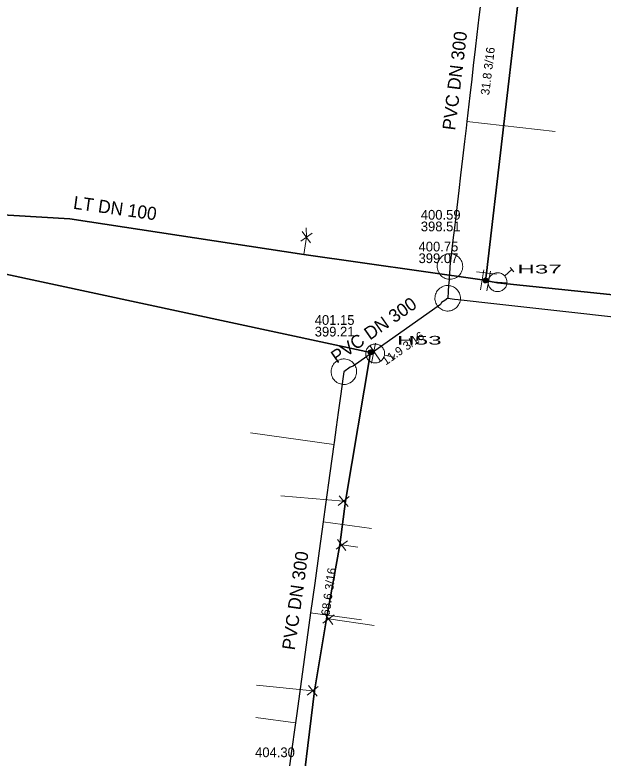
# Model space of a CAD drawing. Extents: x -772952 to -772403, y -1033777 to -1033210.
# Drawn here: x -772682 to -772627.6, y -1033640.4 to -1033571.6 of the extents above; entities that cross this region are included whole.
import ezdxf

# ---------------------------------------------------------------- set-up
doc = ezdxf.new("R2010")
doc.units = 0
doc.header["$LTSCALE"] = 0.36
for name, color, linetype, lineweight in [('15', 7, 'Continuous', 13), ('16', 7, 'Continuous', 35), ('2', 7, 'Continuous', 25), ('20', 7, 'Continuous', 13), ('4', 7, 'Continuous', 13), ('57', 7, 'Continuous', 13), ('59', 7, 'Continuous', 13)]:
    doc.layers.add(name, color=color, linetype=linetype, lineweight=lineweight)
for name, color, linetype in [('17', 7, 'Continuous'), ('3', 7, 'Continuous'), ('6', 7, 'Continuous')]:
    doc.layers.add(name, color=color, linetype=linetype)

msp = doc.modelspace()

# ---------------------------------------------------------------- linework, layer by layer
at = {"layer": '15'}
for p, q in [((-772654.647, -1033592.708), (-772655.418, -1033591.659)), ((-772655.551, -1033592.565), (-772654.509, -1033591.803)), ((-772637.443, -1033595.618), (-772639.293, -1033595.407)), ((-772638.916, -1033597.048), (-772638.603, -1033595.212)), ((-772638.314, -1033597.163), (-772637.977, -1033595.331)), ((-772649.001, -1033603.828), (-772648.632, -1033602.002)), ((-772651.082, -1033616.175), (-772652.077, -1033617.014)), ((-772651.164, -1033617.086), (-772651.993, -1033616.098)), ((-772652.273, -1033621.049), (-772651.237, -1033620.26)), ((-772652.146, -1033620.143), (-772651.367, -1033621.171)), ((-772653.495, -1033627.892), (-772652.455, -1033627.109)), ((-772653.363, -1033626.987), (-772652.589, -1033628.019)), ((-772653.934, -1033633.734), (-772654.943, -1033634.557)), ((-772654.031, -1033634.644), (-772654.844, -1033633.642))]:
    msp.add_line(p, q, dxfattribs=at)
for points in [[(-772638.213, -1033596.194), (-772638.219, -1033596.142), (-772638.236, -1033596.092), (-772638.265, -1033596.048), (-772638.302, -1033596.011), (-772638.347, -1033595.984), (-772638.397, -1033595.967), (-772638.45, -1033595.963), (-772638.502, -1033595.97), (-772638.551, -1033595.989), (-772638.594, -1033596.018), (-772638.63, -1033596.057), (-772638.656, -1033596.102), (-772638.672, -1033596.153), (-772638.675, -1033596.205), (-772638.667, -1033596.257), (-772638.647, -1033596.306), (-772638.616, -1033596.349), (-772638.577, -1033596.383), (-772638.531, -1033596.409), (-772638.48, -1033596.423), (-772638.427, -1033596.425), (-772638.376, -1033596.415), (-772638.328, -1033596.394), (-772638.285, -1033596.363), (-772638.251, -1033596.322), (-772638.227, -1033596.276), (-772638.215, -1033596.225)], [(-772638.243, -1033596.194), (-772638.249, -1033596.145), (-772638.266, -1033596.099), (-772638.294, -1033596.059), (-772638.331, -1033596.027), (-772638.375, -1033596.005), (-772638.423, -1033595.994), (-772638.472, -1033595.994), (-772638.519, -1033596.007), (-772638.562, -1033596.031), (-772638.598, -1033596.064), (-772638.625, -1033596.105), (-772638.641, -1033596.152), (-772638.645, -1033596.201), (-772638.638, -1033596.249), (-772638.619, -1033596.294), (-772638.589, -1033596.334), (-772638.551, -1033596.365), (-772638.507, -1033596.385), (-772638.459, -1033596.395), (-772638.41, -1033596.393), (-772638.363, -1033596.378), (-772638.32, -1033596.353), (-772638.286, -1033596.319), (-772638.26, -1033596.277), (-772638.246, -1033596.23)], [(-772638.273, -1033596.194), (-772638.279, -1033596.149), (-772638.296, -1033596.107), (-772638.324, -1033596.072), (-772638.36, -1033596.045), (-772638.402, -1033596.028), (-772638.447, -1033596.023), (-772638.492, -1033596.029), (-772638.533, -1033596.048), (-772638.568, -1033596.076), (-772638.595, -1033596.113), (-772638.611, -1033596.155), (-772638.615, -1033596.2), (-772638.608, -1033596.245), (-772638.589, -1033596.286), (-772638.56, -1033596.32), (-772638.523, -1033596.346), (-772638.48, -1033596.362), (-772638.435, -1033596.365), (-772638.39, -1033596.357), (-772638.35, -1033596.337), (-772638.316, -1033596.308), (-772638.29, -1033596.27), (-772638.276, -1033596.227)], [(-772638.303, -1033596.194), (-772638.308, -1033596.153), (-772638.326, -1033596.116), (-772638.353, -1033596.085), (-772638.388, -1033596.064), (-772638.428, -1033596.053), (-772638.469, -1033596.055), (-772638.508, -1033596.068), (-772638.542, -1033596.092), (-772638.567, -1033596.124), (-772638.582, -1033596.162), (-772638.585, -1033596.203), (-772638.577, -1033596.243), (-772638.557, -1033596.279), (-772638.528, -1033596.308), (-772638.491, -1033596.327), (-772638.451, -1033596.335), (-772638.41, -1033596.331), (-772638.372, -1033596.316), (-772638.34, -1033596.29), (-772638.317, -1033596.256), (-772638.304, -1033596.217)], [(-772638.333, -1033596.194), (-772638.338, -1033596.158), (-772638.356, -1033596.126), (-772638.382, -1033596.101), (-772638.416, -1033596.086), (-772638.452, -1033596.083), (-772638.487, -1033596.091), (-772638.518, -1033596.111), (-772638.541, -1033596.139), (-772638.554, -1033596.173), (-772638.554, -1033596.21), (-772638.543, -1033596.245), (-772638.522, -1033596.274), (-772638.492, -1033596.295), (-772638.457, -1033596.305), (-772638.42, -1033596.303), (-772638.386, -1033596.289), (-772638.359, -1033596.266), (-772638.34, -1033596.234), (-772638.333, -1033596.199)], [(-772638.363, -1033596.194), (-772638.368, -1033596.163), (-772638.385, -1033596.137), (-772638.411, -1033596.12), (-772638.441, -1033596.113), (-772638.472, -1033596.117), (-772638.499, -1033596.134), (-772638.517, -1033596.158), (-772638.525, -1033596.189), (-772638.521, -1033596.219), (-772638.506, -1033596.247), (-772638.482, -1033596.266), (-772638.452, -1033596.275), (-772638.421, -1033596.272), (-772638.393, -1033596.258), (-772638.373, -1033596.234), (-772638.363, -1033596.205)], [(-772638.393, -1033596.194), (-772638.398, -1033596.17), (-772638.415, -1033596.152), (-772638.438, -1033596.143), (-772638.462, -1033596.146), (-772638.483, -1033596.16), (-772638.494, -1033596.182), (-772638.494, -1033596.207), (-772638.482, -1033596.228), (-772638.462, -1033596.242), (-772638.437, -1033596.245), (-772638.414, -1033596.236), (-772638.398, -1033596.218)], [(-772638.423, -1033596.194), (-772638.428, -1033596.179), (-772638.443, -1033596.173), (-772638.458, -1033596.177), (-772638.465, -1033596.191), (-772638.461, -1033596.206), (-772638.448, -1033596.215), (-772638.433, -1033596.212), (-772638.423, -1033596.2)], [(-772648.857, -1033602.85), (-772648.863, -1033602.798), (-772648.88, -1033602.748), (-772648.909, -1033602.704), (-772648.946, -1033602.667), (-772648.991, -1033602.64), (-772649.041, -1033602.623), (-772649.094, -1033602.619), (-772649.146, -1033602.626), (-772649.195, -1033602.645), (-772649.238, -1033602.674), (-772649.274, -1033602.713), (-772649.3, -1033602.758), (-772649.316, -1033602.809), (-772649.319, -1033602.861), (-772649.311, -1033602.913), (-772649.291, -1033602.962), (-772649.26, -1033603.005), (-772649.221, -1033603.039), (-772649.175, -1033603.065), (-772649.124, -1033603.079), (-772649.071, -1033603.081), (-772649.02, -1033603.071), (-772648.972, -1033603.05), (-772648.929, -1033603.019), (-772648.895, -1033602.978), (-772648.871, -1033602.932), (-772648.858, -1033602.881)], [(-772648.887, -1033602.85), (-772648.893, -1033602.801), (-772648.91, -1033602.755), (-772648.938, -1033602.715), (-772648.975, -1033602.683), (-772649.019, -1033602.661), (-772649.067, -1033602.65), (-772649.116, -1033602.65), (-772649.163, -1033602.663), (-772649.206, -1033602.687), (-772649.242, -1033602.72), (-772649.269, -1033602.761), (-772649.285, -1033602.808), (-772649.289, -1033602.857), (-772649.282, -1033602.905), (-772649.263, -1033602.95), (-772649.233, -1033602.99), (-772649.195, -1033603.021), (-772649.151, -1033603.041), (-772649.103, -1033603.051), (-772649.054, -1033603.049), (-772649.007, -1033603.034), (-772648.964, -1033603.009), (-772648.929, -1033602.975), (-772648.904, -1033602.933), (-772648.89, -1033602.886)], [(-772648.917, -1033602.85), (-772648.923, -1033602.805), (-772648.94, -1033602.763), (-772648.968, -1033602.728), (-772649.004, -1033602.701), (-772649.046, -1033602.684), (-772649.091, -1033602.679), (-772649.136, -1033602.685), (-772649.177, -1033602.704), (-772649.212, -1033602.732), (-772649.239, -1033602.769), (-772649.255, -1033602.811), (-772649.259, -1033602.856), (-772649.252, -1033602.901), (-772649.233, -1033602.942), (-772649.204, -1033602.976), (-772649.167, -1033603.002), (-772649.124, -1033603.018), (-772649.079, -1033603.021), (-772649.034, -1033603.013), (-772648.994, -1033602.993), (-772648.96, -1033602.964), (-772648.934, -1033602.926), (-772648.92, -1033602.883)], [(-772648.947, -1033602.85), (-772648.951, -1033602.809), (-772648.97, -1033602.772), (-772648.997, -1033602.741), (-772649.032, -1033602.72), (-772649.072, -1033602.709), (-772649.113, -1033602.711), (-772649.152, -1033602.724), (-772649.186, -1033602.748), (-772649.211, -1033602.78), (-772649.226, -1033602.818), (-772649.228, -1033602.859), (-772649.221, -1033602.899), (-772649.201, -1033602.935), (-772649.172, -1033602.964), (-772649.135, -1033602.983), (-772649.095, -1033602.991), (-772649.054, -1033602.987), (-772649.016, -1033602.972), (-772648.983, -1033602.946), (-772648.961, -1033602.912), (-772648.948, -1033602.873)], [(-772648.977, -1033602.85), (-772648.982, -1033602.814), (-772649, -1033602.782), (-772649.026, -1033602.757), (-772649.059, -1033602.742), (-772649.096, -1033602.739), (-772649.13, -1033602.747), (-772649.162, -1033602.767), (-772649.184, -1033602.795), (-772649.198, -1033602.829), (-772649.198, -1033602.866), (-772649.187, -1033602.901), (-772649.166, -1033602.93), (-772649.136, -1033602.951), (-772649.101, -1033602.961), (-772649.064, -1033602.959), (-772649.03, -1033602.945), (-772649.003, -1033602.922), (-772648.983, -1033602.89), (-772648.977, -1033602.855)], [(-772649.007, -1033602.85), (-772649.012, -1033602.819), (-772649.029, -1033602.793), (-772649.054, -1033602.776), (-772649.085, -1033602.769), (-772649.116, -1033602.773), (-772649.143, -1033602.79), (-772649.161, -1033602.814), (-772649.169, -1033602.845), (-772649.165, -1033602.875), (-772649.15, -1033602.903), (-772649.125, -1033602.922), (-772649.096, -1033602.931), (-772649.065, -1033602.928), (-772649.037, -1033602.914), (-772649.017, -1033602.89), (-772649.007, -1033602.861)], [(-772649.037, -1033602.85), (-772649.042, -1033602.826), (-772649.059, -1033602.808), (-772649.081, -1033602.799), (-772649.106, -1033602.802), (-772649.127, -1033602.816), (-772649.138, -1033602.838), (-772649.138, -1033602.863), (-772649.125, -1033602.884), (-772649.106, -1033602.898), (-772649.081, -1033602.901), (-772649.058, -1033602.892), (-772649.042, -1033602.874)], [(-772649.067, -1033602.85), (-772649.072, -1033602.835), (-772649.087, -1033602.829), (-772649.102, -1033602.833), (-772649.108, -1033602.847), (-772649.105, -1033602.862), (-772649.092, -1033602.871), (-772649.076, -1033602.868), (-772649.067, -1033602.856)]]:
    msp.add_lwpolyline(points, close=True, dxfattribs=at)
at = {"layer": '16'}
for p in [(-772638.368, -1033595.513), (-772638.76, -1033596.131), (-772638.146, -1033596.248)]:
    msp.add_line(p, (-772638.444, -1033596.194), dxfattribs=at)
for points in [[(-772628.473, -1033511.706), (-772629.473, -1033519.771), (-772631.094, -1033533.208), (-772638.368, -1033595.513)], [(-772871.839, -1033575.434), (-772870.427, -1033576.155), (-772849.008, -1033581.096), (-772841.55, -1033584.107), (-772822.87, -1033596.07), (-772815.517, -1033599.879), (-772800.324, -1033602.374), (-772785.625, -1033603.857), (-772759.69, -1033599.467), (-772726.1, -1033595.877), (-772705.133, -1033594.197), (-772687.467, -1033594.611), (-772649.087, -1033602.85)], [(-772638.76, -1033596.131), (-772655.276, -1033593.796), (-772676.921, -1033590.5), (-772704.421, -1033588.864)], [(-772403.429, -1033620.771), (-772447.891, -1033616.047), (-772451.74, -1033615.638), (-772462.079, -1033614.539), (-772467.47, -1033613.848), (-772520.331, -1033607.07), (-772531.901, -1033605.587), (-772554.774, -1033603.287), (-772583.568, -1033601.986), (-772605.793, -1033599.675), (-772622.201, -1033597.969), (-772637.331, -1033596.399), (-772638.146, -1033596.248)], [(-772667.42, -1033732.259), (-772666.897, -1033730.304), (-772666.388, -1033728.405), (-772663.901, -1033711.543), (-772663.543, -1033708.874), (-772662.528, -1033702.243), (-772661.418, -1033693.445), (-772658.618, -1033672.89), (-772656.675, -1033654.019), (-772655.778, -1033646.539), (-772654.291, -1033634.155), (-772653.179, -1033627.482), (-772651.945, -1033620.636), (-772651.409, -1033616.616), (-772649.087, -1033602.85)]]:
    msp.add_lwpolyline(points, dxfattribs=at)
at = {"layer": '2'}
for points in [[(-772638.919, -1033570.648), (-772639.058, -1033571.841), (-772639.243, -1033573.435), (-772639.4, -1033574.785), (-772639.579, -1033576.32), (-772639.723, -1033577.561), (-772639.899, -1033579.072), (-772640.179, -1033581.479), (-772640.25, -1033582.092), (-772640.394, -1033583.328), (-772640.579, -1033584.921), (-772640.758, -1033586.459), (-772640.921, -1033587.859), (-772641.103, -1033589.43), (-772641.201, -1033590.271), (-772641.353, -1033591.578), (-772641.429, -1033592.226), (-772641.74, -1033594.9)], [(-772641.74, -1033594.9), (-772641.794, -1033595.668), (-772641.801, -1033595.759), (-772641.825, -1033596.095), (-772641.849, -1033596.437), (-772641.863, -1033596.632), (-772641.905, -1033597.218), (-772641.95, -1033597.84)], [(-772641.95, -1033597.84), (-772642.229, -1033598.037), (-772642.524, -1033598.245), (-772642.627, -1033598.426), (-772650.695, -1033604.111), (-772650.968, -1033604.211), (-772651.56, -1033604.63)], [(-772641.95, -1033597.84), (-772641.324, -1033597.909), (-772640.986, -1033597.947), (-772637.393, -1033598.348), (-772633.511, -1033598.781), (-772623.827, -1033599.861), (-772611.029, -1033601.289), (-772607.46, -1033601.687), (-772599.107, -1033602.619), (-772595.732, -1033602.996), (-772594.398, -1033603.145), (-772593.711, -1033603.221), (-772593.01, -1033603.3)], [(-772651.56, -1033604.63), (-772651.679, -1033605.495), (-772651.717, -1033605.774), (-772651.903, -1033607.115), (-772652.079, -1033608.397), (-772652.268, -1033609.761), (-772652.464, -1033611.185), (-772652.49, -1033611.37), (-772652.856, -1033614.025), (-772653.255, -1033616.91), (-772653.475, -1033618.506), (-772653.848, -1033621.205), (-772654.258, -1033624.176), (-772654.637, -1033626.924), (-772655.581, -1033633.763), (-772655.924, -1033636.247), (-772656.043, -1033637.113), (-772656.435, -1033639.951), (-772656.816, -1033642.712), (-772656.941, -1033643.616), (-772656.999, -1033644.037), (-772657.08, -1033644.62)]]:
    msp.add_lwpolyline(points, dxfattribs=at)
at = {"layer": '20'}
for p, q in [((-772636.18, -1033594.978), (-772635.824, -1033595.386)), ((-772636.669, -1033595.762), (-772636.003, -1033595.181)), ((-772636.463, -1033596.404), (-772638.21, -1033596.285)), ((-772648.178, -1033603.67), (-772649.146, -1033602.212)), ((-772647.793, -1033603.116), (-772646.927, -1033603.291)), ((-772646.873, -1033603.027), (-772646.981, -1033603.557))]:
    msp.add_line(p, q, dxfattribs=at)
for points in [[(-772636.758, -1033597.007), (-772636.693, -1033596.945), (-772636.634, -1033596.875), (-772636.582, -1033596.798), (-772636.54, -1033596.719), (-772636.505, -1033596.633), (-772636.479, -1033596.544), (-772636.465, -1033596.454), (-772636.457, -1033596.363), (-772636.462, -1033596.272), (-772636.474, -1033596.182), (-772636.497, -1033596.092), (-772636.528, -1033596.005), (-772636.567, -1033595.923), (-772636.616, -1033595.846), (-772636.673, -1033595.774), (-772636.737, -1033595.707), (-772636.806, -1033595.649), (-772636.882, -1033595.598), (-772636.964, -1033595.555), (-772637.05, -1033595.521), (-772637.138, -1033595.497), (-772637.227, -1033595.479), (-772637.319, -1033595.474), (-772637.41, -1033595.477), (-772637.502, -1033595.49), (-772637.591, -1033595.513), (-772637.675, -1033595.544), (-772637.759, -1033595.585), (-772637.836, -1033595.633), (-772637.909, -1033595.689), (-772637.973, -1033595.753), (-772638.032, -1033595.822), (-772638.084, -1033595.9), (-772638.126, -1033595.979), (-772638.16, -1033596.065), (-772638.186, -1033596.153), (-772638.201, -1033596.243), (-772638.209, -1033596.335), (-772638.204, -1033596.426), (-772638.191, -1033596.516), (-772638.169, -1033596.605), (-772638.138, -1033596.693), (-772638.097, -1033596.773), (-772638.05, -1033596.852), (-772637.992, -1033596.924), (-772637.929, -1033596.99), (-772637.858, -1033597.048), (-772637.783, -1033597.1), (-772637.701, -1033597.142), (-772637.616, -1033597.176), (-772637.528, -1033597.201), (-772637.439, -1033597.218), (-772637.347, -1033597.223), (-772637.256, -1033597.221), (-772637.164, -1033597.207), (-772637.075, -1033597.185), (-772636.99, -1033597.154), (-772636.907, -1033597.113), (-772636.83, -1033597.064), (-772636.759, -1033597.008)], [(-772648.835, -1033603.803), (-772648.746, -1033603.817), (-772648.655, -1033603.821), (-772648.562, -1033603.816), (-772648.474, -1033603.801), (-772648.385, -1033603.776), (-772648.299, -1033603.742), (-772648.218, -1033603.699), (-772648.141, -1033603.65), (-772648.072, -1033603.59), (-772648.008, -1033603.526), (-772647.95, -1033603.454), (-772647.9, -1033603.376), (-772647.859, -1033603.295), (-772647.828, -1033603.209), (-772647.805, -1033603.12), (-772647.791, -1033603.029), (-772647.787, -1033602.938), (-772647.793, -1033602.847), (-772647.809, -1033602.756), (-772647.834, -1033602.667), (-772647.868, -1033602.583), (-772647.909, -1033602.501), (-772647.961, -1033602.425), (-772648.018, -1033602.355), (-772648.084, -1033602.29), (-772648.156, -1033602.233), (-772648.232, -1033602.185), (-772648.316, -1033602.143), (-772648.401, -1033602.112), (-772648.49, -1033602.088), (-772648.58, -1033602.076), (-772648.671, -1033602.072), (-772648.764, -1033602.077), (-772648.852, -1033602.092), (-772648.941, -1033602.117), (-772649.027, -1033602.15), (-772649.108, -1033602.193), (-772649.185, -1033602.243), (-772649.254, -1033602.302), (-772649.318, -1033602.367), (-772649.376, -1033602.439), (-772649.426, -1033602.517), (-772649.465, -1033602.599), (-772649.498, -1033602.684), (-772649.521, -1033602.773), (-772649.535, -1033602.864), (-772649.537, -1033602.955), (-772649.533, -1033603.046), (-772649.517, -1033603.137), (-772649.492, -1033603.226), (-772649.458, -1033603.31), (-772649.417, -1033603.392), (-772649.365, -1033603.468), (-772649.308, -1033603.538), (-772649.242, -1033603.603), (-772649.17, -1033603.66), (-772649.094, -1033603.708), (-772649.01, -1033603.75), (-772648.925, -1033603.781), (-772648.837, -1033603.803)]]:
    msp.add_lwpolyline(points, dxfattribs=at)
at = {"layer": '4'}
for points in [[(-772640.559, -1033594.9), (-772640.566, -1033594.781), (-772640.584, -1033594.664), (-772640.613, -1033594.548), (-772640.654, -1033594.437), (-772640.706, -1033594.33), (-772640.769, -1033594.229), (-772640.842, -1033594.134), (-772640.923, -1033594.048), (-772641.013, -1033593.97), (-772641.111, -1033593.901), (-772641.214, -1033593.843), (-772641.323, -1033593.796), (-772641.437, -1033593.759), (-772641.553, -1033593.734), (-772641.671, -1033593.722), (-772641.79, -1033593.721), (-772641.909, -1033593.732), (-772642.025, -1033593.755), (-772642.139, -1033593.789), (-772642.249, -1033593.835), (-772642.353, -1033593.892), (-772642.452, -1033593.959), (-772642.543, -1033594.035), (-772642.626, -1033594.12), (-772642.7, -1033594.214), (-772642.764, -1033594.314), (-772642.818, -1033594.42), (-772642.861, -1033594.531), (-772642.893, -1033594.645), (-772642.912, -1033594.763), (-772642.92, -1033594.882), (-772642.916, -1033595), (-772642.9, -1033595.118), (-772642.872, -1033595.234), (-772642.833, -1033595.346), (-772642.782, -1033595.454), (-772642.721, -1033595.556), (-772642.65, -1033595.652), (-772642.57, -1033595.739), (-772642.481, -1033595.819), (-772642.385, -1033595.889), (-772642.282, -1033595.949), (-772642.174, -1033595.998), (-772642.061, -1033596.036), (-772641.945, -1033596.062), (-772641.827, -1033596.077), (-772641.708, -1033596.08), (-772641.59, -1033596.071), (-772641.472, -1033596.05), (-772641.358, -1033596.017), (-772641.248, -1033595.973), (-772641.142, -1033595.918), (-772641.043, -1033595.852), (-772640.95, -1033595.777), (-772640.866, -1033595.693), (-772640.791, -1033595.601), (-772640.725, -1033595.502), (-772640.669, -1033595.397), (-772640.625, -1033595.287), (-772640.591, -1033595.173), (-772640.57, -1033595.056), (-772640.559, -1033594.937)], [(-772640.769, -1033597.84), (-772640.776, -1033597.721), (-772640.794, -1033597.604), (-772640.823, -1033597.488), (-772640.864, -1033597.377), (-772640.916, -1033597.27), (-772640.978, -1033597.169), (-772641.051, -1033597.074), (-772641.132, -1033596.988), (-772641.223, -1033596.91), (-772641.321, -1033596.841), (-772641.424, -1033596.783), (-772641.532, -1033596.736), (-772641.647, -1033596.699), (-772641.762, -1033596.674), (-772641.88, -1033596.662), (-772642, -1033596.661), (-772642.119, -1033596.672), (-772642.235, -1033596.695), (-772642.348, -1033596.729), (-772642.458, -1033596.775), (-772642.563, -1033596.832), (-772642.662, -1033596.899), (-772642.752, -1033596.975), (-772642.836, -1033597.06), (-772642.909, -1033597.154), (-772642.973, -1033597.254), (-772643.027, -1033597.36), (-772643.071, -1033597.471), (-772643.103, -1033597.585), (-772643.122, -1033597.703), (-772643.13, -1033597.822), (-772643.125, -1033597.94), (-772643.11, -1033598.058), (-772643.081, -1033598.174), (-772643.043, -1033598.286), (-772642.992, -1033598.394), (-772642.931, -1033598.496), (-772642.86, -1033598.592), (-772642.779, -1033598.679), (-772642.691, -1033598.759), (-772642.595, -1033598.829), (-772642.492, -1033598.889), (-772642.384, -1033598.938), (-772642.271, -1033598.976), (-772642.154, -1033599.002), (-772642.037, -1033599.017), (-772641.918, -1033599.02), (-772641.799, -1033599.011), (-772641.681, -1033598.99), (-772641.568, -1033598.957), (-772641.458, -1033598.913), (-772641.352, -1033598.858), (-772641.252, -1033598.792), (-772641.159, -1033598.717), (-772641.076, -1033598.633), (-772641, -1033598.541), (-772640.934, -1033598.442), (-772640.879, -1033598.337), (-772640.835, -1033598.227), (-772640.801, -1033598.113), (-772640.779, -1033597.996), (-772640.769, -1033597.877)], [(-772650.38, -1033604.63), (-772650.386, -1033604.511), (-772650.404, -1033604.394), (-772650.433, -1033604.278), (-772650.474, -1033604.167), (-772650.526, -1033604.06), (-772650.589, -1033603.959), (-772650.662, -1033603.864), (-772650.743, -1033603.778), (-772650.833, -1033603.7), (-772650.931, -1033603.631), (-772651.034, -1033603.573), (-772651.143, -1033603.526), (-772651.257, -1033603.489), (-772651.373, -1033603.464), (-772651.491, -1033603.452), (-772651.61, -1033603.451), (-772651.729, -1033603.462), (-772651.845, -1033603.485), (-772651.959, -1033603.519), (-772652.069, -1033603.565), (-772652.174, -1033603.622), (-772652.272, -1033603.689), (-772652.363, -1033603.765), (-772652.446, -1033603.85), (-772652.52, -1033603.944), (-772652.584, -1033604.044), (-772652.638, -1033604.15), (-772652.681, -1033604.261), (-772652.713, -1033604.375), (-772652.732, -1033604.493), (-772652.74, -1033604.612), (-772652.736, -1033604.73), (-772652.72, -1033604.848), (-772652.692, -1033604.964), (-772652.653, -1033605.076), (-772652.602, -1033605.184), (-772652.541, -1033605.286), (-772652.47, -1033605.382), (-772652.39, -1033605.469), (-772652.301, -1033605.549), (-772652.205, -1033605.619), (-772652.102, -1033605.679), (-772651.994, -1033605.728), (-772651.881, -1033605.766), (-772651.765, -1033605.792), (-772651.647, -1033605.807), (-772651.528, -1033605.81), (-772651.41, -1033605.801), (-772651.292, -1033605.78), (-772651.178, -1033605.747), (-772651.068, -1033605.703), (-772650.962, -1033605.648), (-772650.863, -1033605.582), (-772650.77, -1033605.507), (-772650.686, -1033605.423), (-772650.611, -1033605.331), (-772650.545, -1033605.232), (-772650.489, -1033605.127), (-772650.445, -1033605.017), (-772650.411, -1033604.903), (-772650.39, -1033604.786), (-772650.38, -1033604.667)]]:
    msp.add_lwpolyline(points, close=True, dxfattribs=at)
at = {"layer": '57'}
for p, q in [((-772640.179, -1033581.479), (-772632, -1033582.42)), ((-772652.49, -1033611.37), (-772660.19, -1033610.3)), ((-772652.49, -1033611.37), (-772660.19, -1033610.3)), ((-772653.475, -1033618.506), (-772648.99, -1033619.13)), ((-772654.637, -1033626.924), (-772649.93, -1033627.58)), ((-772656.043, -1033637.113), (-772659.7, -1033636.61))]:
    msp.add_line(p, q, dxfattribs=at)
at = {"layer": '59'}
msp.add_line((-772637.331, -1033596.399), (-772637.333, -1033596.349), dxfattribs=at)
for points in [[(-772655.277, -1033593.796), (-772655.032, -1033592.185), (-772655.038, -1033591.31)], [(-772649.088, -1033602.85), (-772648.817, -1033602.916), (-772648.663, -1033602.947)], [(-772651.409, -1033616.616), (-772651.579, -1033616.594), (-772657.383, -1033616.1)], [(-772651.945, -1033620.636), (-772651.758, -1033620.656), (-772650.278, -1033620.856)], [(-772653.179, -1033627.482), (-772652.977, -1033627.502), (-772648.743, -1033628.097)], [(-772654.292, -1033634.155), (-772654.438, -1033634.145), (-772659.654, -1033633.616)]]:
    msp.add_lwpolyline(points, dxfattribs=at)

# ---------------------------------------------------------------- texts
at = {"layer": '17'}
msp.add_text('LT DN 100 ', height=1.2, rotation=352, dxfattribs=at).set_placement((-772676.665, -1033589.555))
at = {"layer": '20', "width": 2.1}
for s, p in [('H37 ', (-772635.507, -1033595.544)), ('H53 ', (-772646.631, -1033602.121))]:
    msp.add_text(s, height=0.8, dxfattribs=at).set_placement(p)
at = {"layer": '3'}
for s, height, rotation, p in [('PVC DN 300', 1.2, 83, (-772641.258, -1033582.346)), ('31.8 3/16', 0.8, 83, (-772638.113, -1033579.088)), ('PVC DN 300', 1.2, 35, (-772652.216, -1033603.903)), ('11.9 3/16', 0.8, 35, (-772647.69, -1033604.07)), ('PVC DN 300', 1.2, 82, (-772656.102, -1033630.434)), ('68.6 3/16', 0.8, 82, (-772652.887, -1033627.245))]:
    msp.add_text(s, height=height, rotation=rotation, dxfattribs=at).set_placement(p)
at = {"layer": '6'}
for s, p in [('400.59', (-772644.438, -1033590.567)), ('398.51', (-772644.438, -1033591.644)), ('400.75', (-772644.648, -1033593.508)), ('399.07', (-772644.648, -1033594.585)), ('401.15', (-772654.258, -1033600.297)), ('399.21', (-772654.258, -1033601.374)), ('404.30', (-772659.778, -1033640.287))]:
    msp.add_text(s, height=0.9, dxfattribs=at).set_placement(p)

doc.saveas('drawing.dxf')
